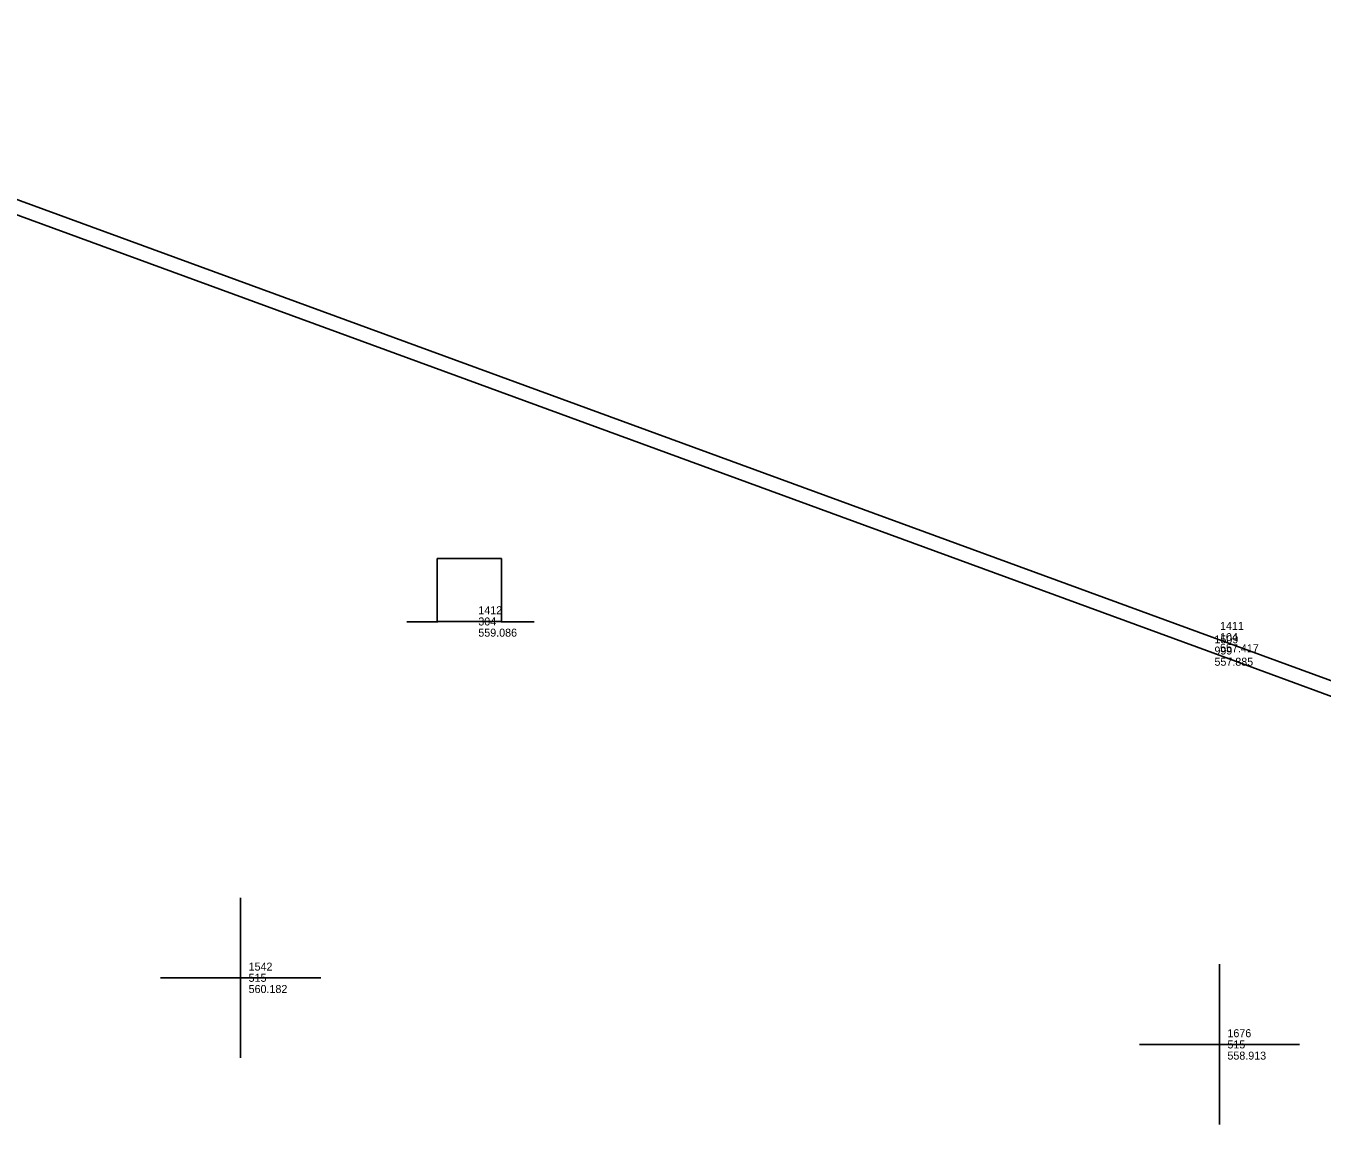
# Model space of a CAD drawing. Extents: x 5447 to 709667, y 4528 to 375505.
# Drawn here: x 707473.55 to 707514.02, y 374468.77 to 374503.72 of the extents above; entities that cross this region are included whole.
import ezdxf

# ---------------------------------------------------------------- set-up
doc = ezdxf.new("R2010")
doc.units = 0
for name, color, linetype in [('SV_BKLN_BKLN', 7, 'Continuous'), ('SV_NODES_ACTIVE_POINT', 7, 'Continuous'), ('SV_NODES_DESCRIPTION', 7, 'Continuous'), ('SV_NODES_ELEVATION', 7, 'Continuous'), ('SV_NODES_PT_NUMBER', 7, 'Continuous'), ('SV_ROAD_BCURB', 7, 'Continuous'), ('SV_SIGN_SIGN', 7, 'Continuous'), ('SV_SURF_SPOT', 7, 'Continuous')]:
    doc.layers.add(name, color=color, linetype=linetype)

msp = doc.modelspace()

# ---------------------------------------------------------------- linework, layer by layer
at = {"layer": 'SV_BKLN_BKLN'}
msp.add_lwpolyline([(707133.67, 374626.44), (707134.797, 374627.639), (707136.583, 374627.954), (707151.798, 374622.764), (707184.947, 374610.643), (707218.65, 374598.11), (707261.132, 374581.647), (707295.83, 374567.872), (707331.755, 374553.554), (707367.93, 374538.946), (707402.359, 374524.852), (707433.104, 374512.816), (707462.931, 374501.61), (707510.412, 374484.217), (707543.749, 374471.971), (707576.321, 374460.095), (707613.615, 374446.485), (707647.59, 374434.202), (707676.48, 374423.509), (707680.643, 374422.011)], dxfattribs=at)
at = {"layer": 'SV_NODES_ACTIVE_POINT'}
for p, q in [((707510.586, 374484.637), (707510.586, 374484.637)), ((707510.412, 374484.217), (707510.412, 374484.217))]:
    msp.add_line(p, q, dxfattribs=at)
at = {"layer": 'SV_ROAD_BCURB'}
msp.add_lwpolyline([(707676.553, 374424.008), (707647.892, 374434.547), (707613.816, 374446.92), (707576.423, 374460.559), (707543.915, 374472.433), (707510.586, 374484.637), (707463.075, 374502.025), (707433.365, 374513.155), (707402.426, 374525.242), (707368.118, 374539.432), (707329.692, 374554.847), (707295.981, 374568.297), (707261.21, 374582.164), (707218.895, 374598.595), (707185.108, 374610.974), (707151.897, 374623.298), (707136.685, 374628.525), (707134.522, 374628.278), (707133.347, 374626.814)], dxfattribs=at)
at = {"layer": 'SV_SIGN_SIGN'}
for p, q in [((707485.44, 374485.112), (707486.413, 374485.112)), ((707488.388, 374485.112), (707489.415, 374485.112))]:
    msp.add_line(p, q, dxfattribs=at)
msp.add_lwpolyline([(707486.391, 374485.122), (707488.394, 374485.122), (707488.394, 374487.09), (707486.391, 374487.09)], close=True, dxfattribs=at)
at = {"layer": 'SV_SURF_SPOT'}
for p, q in [((707480.251, 374471.495), (707480.251, 374476.497)), ((707510.817, 374469.415), (707510.817, 374474.417)), ((707477.75, 374473.996), (707482.752, 374473.996)), ((707480.251, 374473.996), (707480.251, 374473.996)), ((707508.316, 374471.916), (707513.318, 374471.916)), ((707510.817, 374471.916), (707510.817, 374471.916))]:
    msp.add_line(p, q, dxfattribs=at)

# ---------------------------------------------------------------- texts
at = {"layer": 'SV_NODES_DESCRIPTION'}
for s, p in [('304', (707487.674, 374485)), ('104', (707510.836, 374484.512)), ('999', (707510.662, 374484.092)), ('515', (707480.501, 374473.871)), ('515', (707511.067, 374471.791))]:
    msp.add_text(s, height=0.25, dxfattribs=at).set_placement(p)
at = {"layer": 'SV_NODES_ELEVATION'}
for s, p in [('559.086', (707487.674, 374484.65)), ('557.417', (707510.836, 374484.162)), ('557.885', (707510.662, 374483.742)), ('560.182', (707480.501, 374473.521)), ('558.913', (707511.067, 374471.441))]:
    msp.add_text(s, height=0.25, dxfattribs=at).set_placement(p)
at = {"layer": 'SV_NODES_PT_NUMBER'}
for s, p in [('1412', (707487.674, 374485.35)), ('1411', (707510.836, 374484.862)), ('1509', (707510.662, 374484.442)), ('1542', (707480.501, 374474.221)), ('1676', (707511.067, 374472.141))]:
    msp.add_text(s, height=0.25, dxfattribs=at).set_placement(p)

doc.saveas('drawing.dxf')
